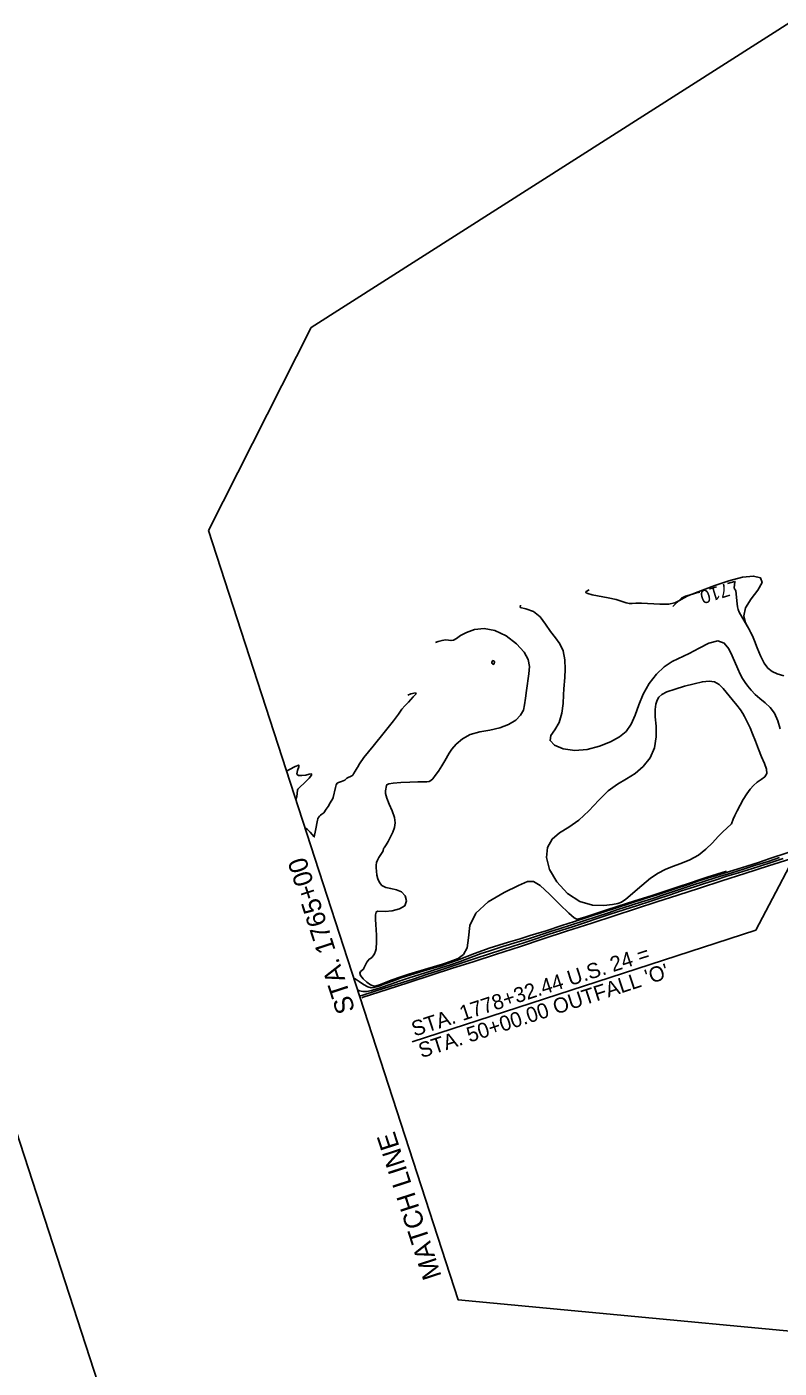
# Model space of a CAD drawing. Extents: x -468541894 to 3393103, y -306086142 to 1227927.
# Drawn here: x 1841121 to 1842984, y 536636 to 539957 of the extents above; entities that cross this region are included whole.
import ezdxf

# ---------------------------------------------------------------- set-up
doc = ezdxf.new("R2010")
doc.units = 0
for name, color, linetype in [('DT_X_Contour_Minor', 7, 'Continuous'), ('DT_X_Terrain_Ground_Line', 7, 'Continuous'), ('Level 14', 7, 'Continuous'), ('Level 19', 7, 'Continuous'), ('Level 40', 7, 'Continuous'), ('SC_Scratch1', 7, 'Continuous'), ('SH_Border', 7, 'Continuous')]:
    doc.layers.add(name, color=color, linetype=linetype)

msp = doc.modelspace()

# ---------------------------------------------------------------- linework, layer by layer
at = {"layer": 'DT_X_Contour_Minor'}
for points in [[(1842513.7, 538563.4), (1842505.8, 538559.1), (1842504.6, 538557.4), (1842506, 538556), (1842510.5, 538553.8), (1842520.9, 538550.9), (1842560.2, 538543.2), (1842580.4, 538538.8), (1842595.2, 538534.4), (1842605.4, 538530.8), (1842612.9, 538528.9), (1842619.7, 538528.9), (1842628.7, 538529.9), (1842642.9, 538530.2), (1842688, 538527.2), (1842709.9, 538527.4), (1842725.7, 538531), (1842737, 538536.6), (1842746.6, 538542.7), (1842757.4, 538547.9), (1842794.2, 538561.8), (1842824.8, 538573.5), (1842859.6, 538585.7), (1842893.3, 538594.7), (1842920.6, 538597.1), (1842937.8, 538592.5), (1842941.7, 538580.8), (1842931.4, 538562.6), (1842914.3, 538540.6), (1842900.3, 538518.3), (1842896.7, 538498.3), (1842900.8, 538481.6), (1842907.6, 538468.4), (1842912.9, 538458.6), (1842917.4, 538449.2), (1842922.4, 538436.8), (1842929.3, 538419.2), (1842937.5, 538399.4), (1842946.5, 538381.6), (1842955.7, 538369.1), (1842966.2, 538360.7), (1842978.9, 538354.7), (1842995.2, 538349.7)], [(1842787, 538557.5), (1842784.4, 538556.7), (1842779.3, 538555.2), (1842774.1, 538553.6), (1842768.9, 538552.1), (1842752, 538547), (1842748.5, 538545.7), (1842745.2, 538544), (1842742.2, 538542), (1842739.4, 538539.5), (1842720.9, 538521.5)], [(1842911.3, 538462.5), (1842888.3, 538501.6), (1842885, 538507.9), (1842882.5, 538514.4), (1842880.7, 538521.1), (1842879.6, 538528.1), (1842876.2, 538560.9), (1842876.2, 538561.1), (1842876.1, 538561.2), (1842876.1, 538561.4), (1842876, 538561.5), (1842875.7, 538561.9), (1842875.6, 538562), (1842875.6, 538562.1), (1842875.5, 538562.2), (1842875.5, 538562.3), (1842873.5, 538565.3), (1842873.2, 538566), (1842872.9, 538566.7), (1842872.8, 538567.4), (1842872.8, 538568.1), (1842874.1, 538582.5), (1842874.1, 538582.6), (1842874.1, 538582.8), (1842874.1, 538583), (1842874.2, 538583.2), (1842874.2, 538583.8), (1842874.2, 538583.9), (1842874.2, 538584), (1842874.1, 538584), (1842874, 538584), (1842856.1, 538578.5)], [(1842343.1, 538524.8), (1842343, 538519.6), (1842356.7, 538516.1), (1842375.4, 538509.6), (1842391.7, 538496), (1842405.3, 538477.9), (1842417.7, 538459.6), (1842430.1, 538444.1), (1842441.1, 538429.3), (1842449.2, 538412), (1842453, 538390.1), (1842453.8, 538366.6), (1842452.9, 538346), (1842450.7, 538318.3), (1842449.7, 538303.1), (1842448.7, 538281.8), (1842445.9, 538257.5), (1842439.3, 538234.6), (1842428.4, 538216.4), (1842418.5, 538202.1), (1842416.5, 538189.8), (1842427.6, 538178.3), (1842449.4, 538169.3), (1842477.7, 538165.4), (1842508.6, 538168.1), (1842539, 538176.1), (1842566.3, 538186.8), (1842588.2, 538198.7), (1842605, 538212.6), (1842617.6, 538230.3), (1842627.2, 538252.6), (1842636.1, 538278.1), (1842647, 538305), (1842662, 538331), (1842680, 538354.3), (1842699.3, 538372.8), (1842718.6, 538385.3), (1842760.8, 538405.2), (1842785.5, 538418.7), (1842810.1, 538431), (1842831.7, 538436.4), (1842847.8, 538430.8), (1842859.3, 538416.9), (1842867.8, 538399.6), (1842881.2, 538367.5), (1842887.1, 538354.3), (1842893, 538343.4), (1842899.4, 538333.9), (1842906.5, 538324.6), (1842914.9, 538314.5), (1842924.7, 538304), (1842936.1, 538293.6), (1842948.8, 538283.3), (1842961.6, 538271.8), (1842972.6, 538257.4), (1842980.6, 538239), (1842986.3, 538218.9)], [(1842009.4, 538058.4), (1842009.2, 538065.6), (1842011.3, 538078.4), (1842012.6, 538080.5), (1842017.3, 538082.4), (1842028.2, 538084.2), (1842046.9, 538085.7), (1842069.1, 538086.8), (1842089.4, 538087.4), (1842111.8, 538087.5), (1842117.3, 538088.3), (1842121.8, 538090.6), (1842126.5, 538095.2), (1842132.5, 538103), (1842140.4, 538114.5), (1842148.9, 538127.6), (1842156.4, 538139.9), (1842166.5, 538158.4), (1842173.4, 538168.4), (1842184.3, 538181), (1842199.5, 538194.2), (1842219.1, 538205), (1842242.5, 538211.6), (1842267.8, 538216), (1842292.4, 538221.2), (1842314, 538229.6), (1842331.5, 538240.6), (1842343.8, 538252.7), (1842350.6, 538265.1), (1842353.7, 538278.7), (1842355.6, 538294.8), (1842358.2, 538314.2), (1842364.2, 538355.3), (1842365.5, 538373.2), (1842362.5, 538390.2), (1842352.5, 538408.6), (1842333.4, 538429.3), (1842308, 538448.9), (1842280.2, 538462.7), (1842253.3, 538467.3), (1842229.2, 538464.6), (1842209.5, 538457.7), (1842195.2, 538449.7), (1842185.2, 538442.5), (1842177.9, 538438), (1842171.7, 538437.2), (1842165.4, 538438.4), (1842158.1, 538439.2), (1842149.1, 538437.8), (1842139.8, 538434.9), (1842133, 538432.5)], [(1842274.2, 538387.4), (1842275.7, 538387.7), (1842276.5, 538387.5), (1842278.1, 538386.6), (1842278.9, 538385.4), (1842278.8, 538383.2), (1842278.4, 538381.2), (1842277.7, 538379.2), (1842276.6, 538378.2), (1842275, 538378.9), (1842273.5, 538380.7), (1842272.5, 538382.8), (1842272.4, 538384.6), (1842273, 538385.9), (1842274.2, 538387.4)], [(1842865.6, 537983.7), (1842854.1, 537973.3), (1842844.7, 537964.2), (1842832.9, 537952), (1842818.9, 537936.9), (1842802.6, 537920.8), (1842783.7, 537906.1), (1842762.4, 537894.6), (1842740.3, 537885.7), (1842719.5, 537878.2), (1842701.4, 537870.8), (1842684.1, 537861.8), (1842665.3, 537848.9), (1842643.5, 537831.4), (1842604.2, 537797.6), (1842593.1, 537789.4), (1842584.2, 537786.2), (1842571.1, 537784.3), (1842549.5, 537781.8), (1842521.3, 537782.5), (1842490.2, 537791.3), (1842459.7, 537811.6), (1842433.6, 537840), (1842415.3, 537871), (1842407.7, 537900.1), (1842410.2, 537925.4), (1842421.5, 537945.9), (1842439.9, 537961.4), (1842463, 537975.5), (1842488.1, 537992.8), (1842513, 538016.2), (1842537.2, 538042.1), (1842560.7, 538065.2), (1842583.5, 538081.9), (1842605.5, 538094.8), (1842626.9, 538108.2), (1842647.1, 538125.5), (1842664.2, 538146.8), (1842675.5, 538171.6), (1842679.6, 538198.7), (1842679, 538225.5), (1842677.2, 538249), (1842677, 538266.9), (1842678.7, 538279.8), (1842681.7, 538289.5), (1842685.8, 538297.2), (1842693.2, 538303.9), (1842706.1, 538310.5), (1842726, 538317.4), (1842749.8, 538324.3), (1842773.5, 538330.5), (1842793.8, 538335.3), (1842810.4, 538337.3), (1842824, 538335.5), (1842835.3, 538328.9), (1842845.5, 538318.4), (1842867.4, 538291.4), (1842878.7, 538277.7), (1842888, 538265.8), (1842894.2, 538256.7), (1842898.2, 538249.2), (1842906.3, 538232.7), (1842911.8, 538221.3), (1842918.2, 538206.7), (1842925.2, 538188.7), (1842932.7, 538168.9), (1842940.2, 538149.7), (1842947.4, 538132.9), (1842952.3, 538118.9), (1842953, 538108), (1842948.2, 538099.8), (1842939.5, 538093.1), (1842929.6, 538086.6), (1842920.3, 538078.8), (1842911.8, 538069.3), (1842903.4, 538057.7), (1842895, 538044.1), (1842886.9, 538029.7), (1842879.8, 538016), (1842874.3, 538004.2), (1842870.2, 537994.9), (1842865.6, 537983.7)], [(1842064.8, 538302.6), (1842072, 538305.2), (1842083.3, 538307.7), (1842084.7, 538305.9), (1842077.8, 538297.8), (1842065.8, 538285), (1842057, 538275.7), (1842050, 538267.9), (1842046.1, 538262.7), (1842041.1, 538255.2), (1842028.8, 538238.8), (1842005.8, 538210), (1841978.6, 538176.2), (1841955.9, 538147.7), (1841944.4, 538132.1), (1841941.3, 538126.6), (1841941.9, 538126), (1841941.8, 538125.6), (1841939, 538122), (1841934.4, 538114.4), (1841930.2, 538107.2), (1841928.2, 538104.6), (1841925.8, 538102.7), (1841922.8, 538101.2), (1841916.4, 538098.3), (1841913.7, 538096.4), (1841908.3, 538092), (1841904.6, 538089.9), (1841900.6, 538088.2), (1841892.9, 538085.9), (1841889.9, 538084.1), (1841887.3, 538080.2), (1841885.1, 538073.5), (1841879.6, 538048.7), (1841878.6, 538046.4), (1841872.1, 538035.6), (1841867.1, 538026.5), (1841862.6, 538019.8), (1841856.2, 538011.2), (1841851.2, 538007.4), (1841848.5, 538005.4), (1841846, 538003), (1841844, 538000.6), (1841842.5, 537998.3), (1841841.5, 537996), (1841840.7, 537992.5), (1841835.9, 537966.9), (1841832.7, 537951.5), (1841822.9, 537962.9), (1841816.1, 537969.7), (1841810, 537973.7)], [(1841764.4, 538114), (1841771.3, 538118), (1841785.6, 538126), (1841794.4, 538129), (1841795, 538124.6), (1841791.4, 538116.1), (1841789.4, 538107.9), (1841793.3, 538103.7), (1841801.8, 538103.1), (1841811.7, 538104.6), (1841820.6, 538106.6), (1841826, 538107.2), (1841826.1, 538104.4), (1841819.9, 538096.8), (1841810.2, 538087), (1841795.2, 538072.9), (1841792.5, 538069.9), (1841791.5, 538067), (1841789.6, 538051.5), (1841788.2, 538046.2), (1841787.3, 538043.7)], [(1842853.4, 537866.3), (1842805.2, 537851.4), (1842785.6, 537844.9), (1842761.8, 537837), (1842734, 537827.8), (1842686.5, 537812.1), (1842669.6, 537806.7), (1842626.2, 537792.8), (1842585.5, 537779.7), (1842552, 537768.9), (1842505.2, 537753.6), (1842485.6, 537747.3), (1842483.1, 537747.3), (1842476.6, 537751.1), (1842463, 537762.8), (1842440.9, 537784.3), (1842415.1, 537809.7), (1842392.1, 537830.7), (1842376, 537841.1), (1842360.8, 537840.7), (1842338.1, 537831.1), (1842302.7, 537813.8), (1842263.5, 537790.4), (1842232.5, 537762.4), (1842218.1, 537731.7), (1842214.3, 537701.9), (1842211.4, 537677.1), (1842202.1, 537660.4), (1842188.8, 537650.5), (1842176.2, 537645), (1842160.1, 537639.2), (1842149.9, 537636), (1842114.4, 537625.5), (1842067.1, 537611.5), (1842044.6, 537604.5), (1842025.4, 537597.2), (1841994.2, 537585.1), (1841986.3, 537582.4), (1841983.2, 537581.7), (1841978.9, 537582.3), (1841972.4, 537585.4), (1841963.2, 537591.8), (1841953.6, 537600), (1841946.9, 537607.9), (1841945.3, 537613.8), (1841947.4, 537617.8), (1841954.3, 537624.2), (1841955.7, 537626.3), (1841963.1, 537641.1), (1841966.2, 537645.7), (1841969.1, 537648.3), (1841972, 537650), (1841975.1, 537652.5), (1841978.7, 537656.7), (1841982, 537662.2), (1841984.6, 537668.2), (1841985.8, 537673.9), (1841987, 537691.8), (1841987.2, 537698.5), (1841987, 537708.5), (1841985.6, 537734.1), (1841984.8, 537747.2), (1841984.6, 537758.2), (1841985.9, 537765.4), (1841989.6, 537767.8), (1842008.7, 537766.7), (1842025.7, 537768.3), (1842043.5, 537772.9), (1842056.7, 537781.1), (1842061.4, 537792.7), (1842058.2, 537805.2), (1842049.2, 537815.2), (1842036.4, 537820.7), (1842022.3, 537823.3), (1842009.6, 537826.2), (1842000.3, 537831.4), (1841994.1, 537838.8), (1841990.2, 537847.6), (1841987.8, 537857), (1841986.5, 537866.2), (1841985.9, 537874.6), (1841985.9, 537881.6), (1841986.8, 537887.8), (1841989.1, 537893.8), (1841993, 537900.3), (1842001.2, 537912.5), (1842003.2, 537917.2), (1842004.6, 537923), (1842005.5, 537924.4), (1842007.4, 537926.6), (1842010.7, 537931.4), (1842015.9, 537940.1), (1842021.9, 537951.3), (1842027.5, 537963.2), (1842031.7, 537974.5), (1842033.3, 537986.1), (1842031.5, 537999.6), (1842025.7, 538015.8), (1842018.3, 538032.8), (1842012.2, 538047.6), (1842009.4, 538058.4)], [(1843006.4, 537913.1), (1842960.7, 537897.6), (1842932.3, 537888.2), (1842903.7, 537879.3), (1842882.1, 537872.6), (1842836.6, 537858.6), (1842806.2, 537849), (1842785.3, 537842.2), (1842764.3, 537835.2), (1842719.1, 537820.3), (1842681.7, 537808), (1842652.4, 537798.5), (1842614.5, 537786.4), (1842581.5, 537775.7), (1842550.5, 537765.6), (1842510.2, 537752.5), (1842477.1, 537741.8), (1842446.1, 537731.8), (1842406.6, 537719.2), (1842381.5, 537711.2), (1842367.2, 537706.9), (1842342.6, 537699.4), (1842313.9, 537690.7), (1842266.2, 537676.2), (1842259.1, 537673.7), (1842229.6, 537662.4), (1842187.7, 537646.4), (1842165.7, 537638.5), (1842144.6, 537631.7), (1842112.1, 537622), (1842071.6, 537609.9), (1842048.3, 537602.6), (1842029.2, 537595.4), (1842007.9, 537587.3), (1841992.4, 537581.9), (1841986.2, 537580), (1841980.2, 537578.3), (1841973.5, 537578), (1841965.2, 537580.5), (1841955, 537586.3), (1841944.1, 537593.6), (1841934.4, 537599.6), (1841931, 537600.9)], [(1842984.5, 537900.2), (1842956.3, 537890.8), (1842923, 537880.3), (1842897.8, 537872.4), (1842866.5, 537862.7), (1842827.8, 537850.6), (1842797.4, 537840.8), (1842769.3, 537831.6), (1842737.1, 537821), (1842702.1, 537809.5), (1842671.1, 537799.2), (1842644.1, 537790.5), (1842618, 537782.2), (1842584.8, 537771.5), (1842561.1, 537763.6), (1842533.6, 537754.7), (1842498, 537743), (1842467.3, 537733), (1842441.8, 537724.8), (1842414.8, 537716.1), (1842385.5, 537706.6), (1842365.4, 537699.9), (1842335, 537690.4), (1842299.9, 537679.7), (1842265.3, 537668.8), (1842246.2, 537662.3), (1842222.1, 537653.4), (1842194.4, 537643.2), (1842170.1, 537634.9), (1842146.4, 537627.1), (1842120.8, 537619), (1842093.9, 537610.8), (1842067.7, 537602.6), (1842045.4, 537595.1), (1842020.2, 537586), (1841998.2, 537578.9), (1841974.4, 537571.4), (1841963.3, 537568.9), (1841953.4, 537568.4), (1841944.9, 537570.6), (1841940, 537573.1)], [(1841945.1, 537557.4), (1841953.2, 537559.7), (1841986.1, 537570.1), (1842020.2, 537580.9), (1842051.3, 537590.9), (1842077.3, 537599.5), (1842110.5, 537610.4), (1842139.6, 537619.8), (1842174.6, 537631.2), (1842208.7, 537642.5), (1842233.3, 537651), (1842264.5, 537661.4), (1842297.5, 537672), (1842327.5, 537681.4), (1842349.4, 537688.6), (1842381.5, 537699.4), (1842411.8, 537709.4), (1842445.6, 537720.4), (1842472.1, 537729), (1842504.4, 537739.6), (1842538.3, 537750.7), (1842565.4, 537759.7), (1842599, 537770.7), (1842633, 537781.6), (1842663.7, 537791.4), (1842683.1, 537797.9), (1842711.3, 537807.4), (1842742, 537817.5), (1842774.4, 537828), (1842796.1, 537835.1), (1842825.1, 537844.4), (1842854.5, 537853.8), (1842882.9, 537862.7), (1842904.4, 537869.4), (1842935.6, 537879.2), (1842966.3, 537888.9), (1842993.9, 537897.9)]]:
    msp.add_lwpolyline(points, dxfattribs=at)
at = {"layer": 'DT_X_Terrain_Ground_Line'}
msp.add_line((1842189.3, 536805.3), (1841571, 538709.7), dxfattribs=at)
at = {"layer": 'Level 14'}
msp.add_lwpolyline([(1841950.3, 537553.2), (1841953.7, 537554.3), (1842013.4, 537573.8), (1842067.2, 537591.1), (1842124.8, 537609.8), (1842172.5, 537625.3), (1842229, 537643.2), (1842281.9, 537660.5), (1842343.4, 537680.4), (1842399.6, 537698.8), (1842457.1, 537717.8), (1842520.1, 537738.1), (1842575.1, 537756), (1842630.7, 537774.2), (1842681.1, 537790.4), (1842732.6, 537807.2), (1842786.6, 537824.5), (1842841.6, 537842.3), (1842899.1, 537860.9), (1842957.3, 537879.6), (1843012.5, 537897.4)], dxfattribs=at)
at = {"layer": 'Level 40'}
for p, q in [((1842926, 537720.4), (1843152.9, 538152.3)), ((1842074.9, 537444.1), (1842926, 537720.4))]:
    msp.add_line(p, q, dxfattribs=at)
at = {"layer": 'SC_Scratch1'}
msp.add_lwpolyline([(1841571, 538709.7), (1842189.3, 536805.3), (1843431.2, 536688.2), (1846191.5, 536987.1), (1848203, 537933.4), (1849637.7, 539126.1), (1848778.3, 540555.8), (1848707.4, 540644.4), (1847509.3, 542205.2), (1846552.9, 542298.5), (1845079.9, 541287.2), (1841825, 539212.4)], close=True, dxfattribs=at)
at = {"layer": 'SH_Border'}
for points in [[(1839827.6, 541125.5), (1848958.4, 544089.9), (1850903.8, 538097.8), (1841773, 535133.4)], [(1839542.2, 541032.9), (1839827.6, 541125.5), (1841773, 535133.4), (1841487.6, 535040.8)]]:
    msp.add_lwpolyline(points, close=True, dxfattribs=at)

# ---------------------------------------------------------------- texts
at = {"layer": 'DT_X_Terrain_Ground_Line'}
msp.add_text('MATCH LINE                  STA. 1765+00', height=46.8, rotation=107.9864, dxfattribs=at).set_placement((1842148.3, 536864.1))
at = {"layer": 'Level 19'}
msp.add_text('710', height=33, rotation=196.9149, dxfattribs=at).set_placement((1842855.2, 538580.3))
at = {"layer": 'Level 40'}
for s, p in [('STA. 1778+32.44 U.S. 24 =', (1842080.6, 537456.8)), ("STA. 50+00.00 OUTFALL 'O'", (1842098, 537403.3))]:
    msp.add_text(s, height=37.5, rotation=17.9864, dxfattribs=at).set_placement(p)

doc.saveas('drawing.dxf')
